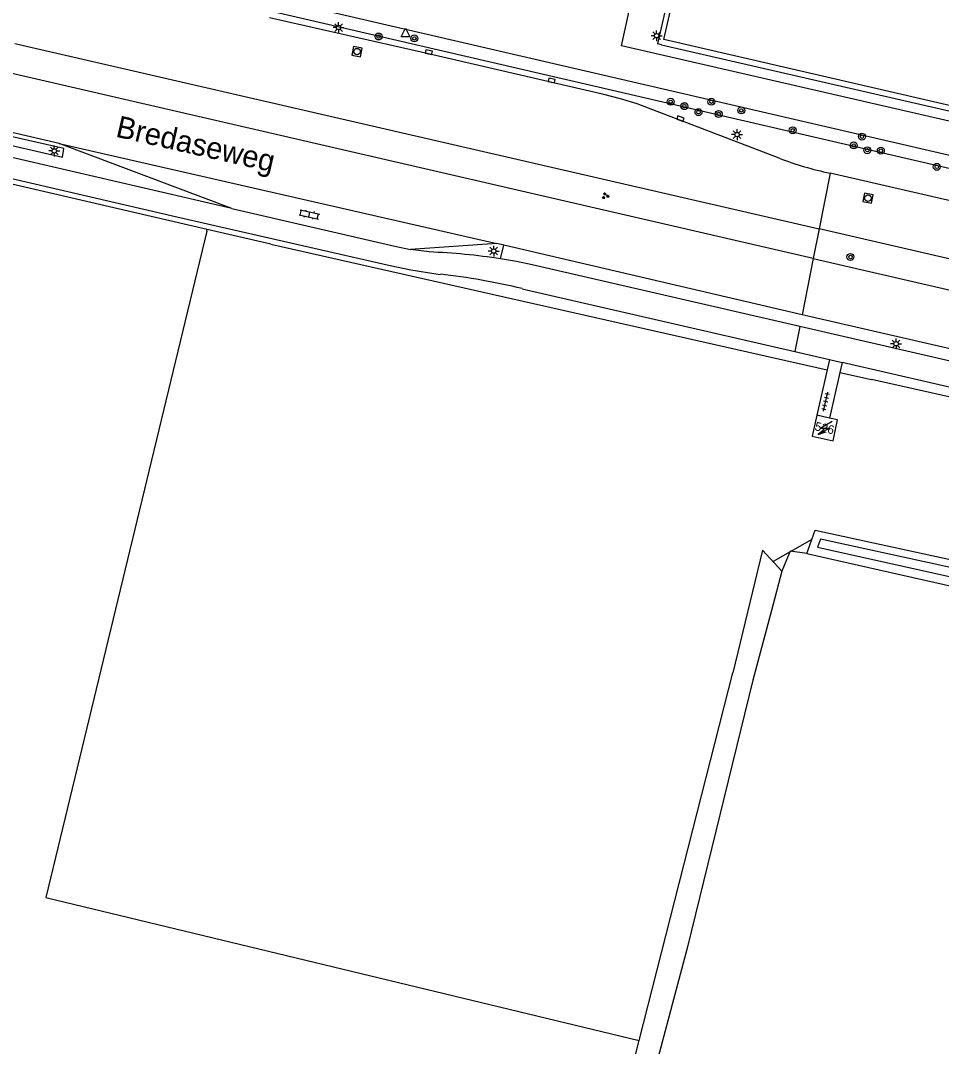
# Model space of a CAD drawing. Extents: x 128999 to 131010, y 395498 to 399007.
# Drawn here: x 129830.6 to 129936.7, y 396799.6 to 396917.8 of the extents above; entities that cross this region are included whole.
import ezdxf

# ---------------------------------------------------------------- set-up
doc = ezdxf.new("R2010")
doc.units = 0
for name, color, linetype in [('gg-afsc-hekwerk', 7, 'Continuous'), ('gg-anno-huisnummerreeks BGT', 7, 'Continuous'), ('gg-anno-openbare ruimte label', 7, 'Continuous'), ('gg-bbg-hoofdgebouw', 7, 'Continuous'), ('gg-knt-verharding', 7, 'Continuous'), ('gg-kntw-bovenkant insteek waterloop', 7, 'Continuous'), ('gg-kntw-waterlijn', 7, 'Continuous'), ('gg-kwrk-duiker nz buis', 7, 'Continuous'), ('gt-grn-groengrens', 7, 'Continuous'), ('gt-grn-weggrens', 7, 'Continuous'), ('gt-symb-boom', 7, 'Continuous'), ('gt-symb-groenvak', 7, 'Continuous'), ('gt-symb-klinker verharding', 7, 'Continuous'), ('gt-symb-kolk', 7, 'Continuous'), ('gt-symb-lichtmast', 7, 'Continuous'), ('gt-symb-rioolschacht', 7, 'Continuous'), ('gt-symb-tegel verharding', 7, 'Continuous'), ('gt-symb-trafo symbool', 7, 'Continuous'), ('gt-symb-waterafsluiter', 7, 'Continuous'), ('gx-grn-maaiveld', 7, 'Continuous')]:
    doc.layers.add(name, color=color, linetype=linetype)

# ---------------------------------------------------------------- blocks, each defined once
blk = doc.blocks.new('gt0-LMAST')
at = {"layer": 'gt-symb-lichtmast'}
for p, q in [((-0.18, 0.17), (-0.45, 0.44)), ((-0.01, 0.25), (-0.01, 0.62)), ((0.17, 0.17), (0.44, 0.44)), ((-0.26, 0), (-0.63, 0)), ((-0.18, -0.18), (-0.45, -0.45)), ((-0.01, -0.25), (-0.01, -0.63)), ((0.44, -0.45), (0.17, -0.18)), ((0.24, 0), (0.62, 0))]:
    blk.add_line(p, q, dxfattribs=at)
blk.add_circle((-0.01, 0), 0.25, dxfattribs=at)
blk = doc.blocks.new('gt0-BOOM')
at = {"layer": 'gt-symb-boom'}
for radius in [0.4, 0.2]:
    blk.add_circle((0, 0), radius, dxfattribs=at)
blk = doc.blocks.new('gt0-KOLK')
at = {"layer": 'gt-symb-kolk'}
blk.add_lwpolyline([(0, 0), (0.38, 0), (0.38, 0.4), (-0.38, 0.4), (-0.38, 0), (0, 0)], dxfattribs=at)
blk = doc.blocks.new('gt0-RS')
at = {"layer": 'gt-symb-rioolschacht'}
blk.add_lwpolyline([(-0.5, -0.5), (0.5, -0.5), (0.5, 0.5), (-0.5, 0.5)], close=True, dxfattribs=at)
blk.add_circle((0, 0), 0.375, dxfattribs=at)
blk = doc.blocks.new('gt0-WAFSL')
at = {"layer": 'gt-symb-waterafsluiter'}
for p, q in [((-0.5, -0.33), (0, 0.67)), ((0, 0.67), (0.5, -0.33)), ((0.5, -0.33), (-0.5, -0.33))]:
    blk.add_line(p, q, dxfattribs=at)
blk = doc.blocks.new('gt0-KL1')
at = {"layer": 'gt-symb-klinker verharding'}
for p, q in [((-1.15, 0.3), (1.15, 0.3)), ((-1, -0.3), (-1, 0.3)), ((-0.5, 0.3), (-0.5, 0.45)), ((0, -0.3), (0, 0.3)), ((0.5, 0.3), (0.5, 0.45)), ((1, -0.3), (1, 0.3)), ((-1.15, -0.3), (1.15, -0.3)), ((-0.5, -0.45), (-0.5, -0.3)), ((0.5, -0.45), (0.5, -0.3))]:
    blk.add_line(p, q, dxfattribs=at)
blk = doc.blocks.new('gt0-GRVAK')
at = {"layer": 'gt-symb-groenvak'}
for p, q in [((-0.11, 0.19), (-0.23, 0.24)), ((-0.18, 0.15), (0.09, 0.15)), ((-0.09, 0.21), (-0.16, 0.32)), ((-0.05, 0.21), (-0.05, 0.39)), ((0, 0.21), (0.06, 0.32)), ((0.01, 0.19), (0.13, 0.24)), ((0.26, -0.05), (0.2, 0.06)), ((0.31, -0.05), (0.31, 0.13)), ((0.35, -0.05), (0.41, 0.06)), ((-0.24, -0.23), (-0.36, -0.18)), ((-0.32, -0.26), (-0.05, -0.26)), ((-0.23, -0.21), (-0.29, -0.1)), ((-0.18, -0.2), (-0.18, -0.02)), ((-0.14, -0.21), (-0.07, -0.1)), ((-0.12, -0.23), (0, -0.18)), ((0.24, -0.07), (0.12, -0.02)), ((0.17, -0.11), (0.44, -0.11)), ((0.37, -0.07), (0.49, -0.02))]:
    blk.add_line(p, q, dxfattribs=at)
blk = doc.blocks.new('gt0-HSP')
at = {"layer": 'gt-symb-trafo symbool'}
for points in [[(0.77, 0.75), (-0.53, 0), (0.47, 0), (-0.83, -0.75)], [(-0.22, -0.24), (-0.83, -0.75), (-0.08, -0.48)]]:
    blk.add_lwpolyline(points, dxfattribs=at)
blk = doc.blocks.new('gt0-TEG1')
at = {"layer": 'gt-symb-tegel verharding'}
for p, q in [((-1.12, 0), (1.12, 0)), ((-0.9, -0.25), (-0.9, 0.25)), ((-0.45, -0.25), (-0.45, 0.25)), ((0, -0.25), (0, 0.25)), ((0.45, -0.25), (0.45, 0.25)), ((0.9, -0.25), (0.9, 0.25))]:
    blk.add_line(p, q, dxfattribs=at)

msp = doc.modelspace()

# ---------------------------------------------------------------- linework, layer by layer
at = {"layer": 'gg-afsc-hekwerk'}
for p, q in [((129904.46, 396915.02), (129961.08, 396901.99)), ((129852.09, 396893.73), (129798.43, 396906.18)), ((129852.09, 396893.73), (129798.43, 396906.18)), ((129859.43, 396892.03), (129852.09, 396893.73)), ((129859.43, 396892.03), (129852.09, 396893.73))]:
    msp.add_line(p, q, dxfattribs=at)
for points in [[(129904.46, 396915.02), (129904.01, 396915.13), (129926.28, 397012.22), (129944.93, 397007.94)], [(129961.99, 396900.62), (129899.85, 396914.88), (129901.75, 396923.71), (129893.46, 396925.54), (129893.84, 396927.48)]]:
    msp.add_lwpolyline(points, dxfattribs=at)
at = {"layer": 'gg-bbg-hoofdgebouw'}
msp.add_line((129923.81, 396871.98), (129922.35, 396872.32), dxfattribs=at)
msp.add_lwpolyline([(129922.35, 396872.32), (129921.79, 396869.92), (129924.21, 396869.37), (129924.74, 396871.77), (129923.81, 396871.98)], dxfattribs=at)
at = {"layer": 'gg-knt-verharding'}
for p, q in [((129921.93, 396890.37), (129811.75, 396915.82)), ((129829.95, 396915.16), (129922.61, 396893.79)), ((129835.03, 396903.64), (129808.32, 396909.88)), ((129798.58, 396906.82), (129848.6, 396895.2)), ((129835.03, 396903.64), (129885.46, 396892.1)), ((129854.94, 396896.15), (129835.03, 396903.64)), ((129976.57, 396888.09), (129923.88, 396900.23)), ((129991.44, 396877.96), (129922.61, 396893.79)), ((129885.46, 396892.1), (129875.51, 396891.44)), ((129886.26, 396891.91), (129885.46, 396892.1)), ((129877.68, 396891.14), (129875.51, 396891.44)), ((129920.65, 396883.88), (129886.26, 396891.91)), ((129921.93, 396890.37), (129990.62, 396874.57)), ((129888.38, 396886.9), (129919.81, 396879.66)), ((129919.81, 396879.66), (129923.81, 396878.74)), ((129923.81, 396878.74), (129923.54, 396877.56)), ((129923.81, 396878.74), (129925.27, 396878.41)), ((129925.27, 396878.41), (129925, 396877.24)), ((129923.54, 396877.56), (129922.35, 396872.32)), ((129925, 396877.24), (129923.81, 396871.98))]:
    msp.add_line(p, q, dxfattribs=at)
for points in [[(129926.73, 397011.51), (129983.36, 396998.53), (129961.2, 396902.58), (129904.71, 396915.61), (129926.73, 397011.51)], [(129918.02, 396901.95), (129901.63, 396908.2), (129899.73, 396908.78), (129897.81, 396909.28), (129877.59, 396913.97), (129859.29, 396918.13)], [(129854.94, 396896.15), (129809.83, 396906.58), (129808.62, 396906.81)], [(129854.94, 396896.15), (129873.72, 396891.81), (129875.51, 396891.44)], [(129848.6, 396895.2), (129873.17, 396889.57), (129875.56, 396889.08), (129878.96, 396888.55)], [(129920.38, 396882.54), (129889.54, 396889.65), (129887.73, 396890.02), (129885.9, 396890.33)], [(130090.42, 396844.78), (130000, 396865.64), (129920.65, 396883.88)], [(130090.09, 396843.43), (130000, 396864.17), (129920.38, 396882.54)], [(130328.39, 396785.64), (130000, 396861.19), (129925.27, 396878.41)]]:
    msp.add_lwpolyline(points, dxfattribs=at)
for centre, radius, start, end in [((129931.37, 396936.5), 37.04, 248.8743, 258.3329), ((129875.09, 396822.68), 68.51, 80.9178, 87.8349), ((129871.15, 396816.17), 72.81, 76.3037, 83.8406)]:
    msp.add_arc(centre, radius, start, end, dxfattribs=at)
at = {"layer": 'gg-kntw-bovenkant insteek waterloop'}
for p, q in [((129918.31, 396854.36), (129917.11, 396849.83)), ((129917.11, 396849.83), (129914.98, 396841.78)), ((129901.86, 396800.25), (129912.65, 396842.64))]:
    msp.add_line(p, q, dxfattribs=at)
for points in [[(129918.31, 396854.36), (129916.1, 396856.75), (129912.65, 396842.64)], [(129914.98, 396841.78), (129907.4, 396810.88), (129901.52, 396788.8), (129891.75, 396746.48), (129886.76, 396727.57)], [(129885.5, 396722.82), (129883.07, 396723.36), (129889.98, 396751.46), (129897.32, 396782.44), (129901.86, 396800.25)]]:
    msp.add_lwpolyline(points, dxfattribs=at)
at = {"layer": 'gg-kntw-waterlijn'}
msp.add_lwpolyline([(129984.76, 396853.77), (129982.71, 396846.2), (129981.68, 396845.44), (129980.18, 396845.51), (129922.77, 396858.02), (129922.42, 396857.11), (129980.65, 396844.18), (129982.08, 396844.15), (129983.75, 396845.55), (129986.06, 396853.36)], dxfattribs=at)
at = {"layer": 'gg-kwrk-duiker nz buis'}
msp.add_line((129921.77, 396858), (129917.3, 396855.45), dxfattribs=at)
at = {"layer": 'gt-grn-groengrens'}
for p, q in [((129859.21, 396918.95), (129977.49, 396891.52)), ((129852.05, 396893.55), (129852.09, 396893.73)), ((129922.61, 396893.79), (129921.93, 396890.37)), ((129859.43, 396892.03), (129923.54, 396877.56)), ((129885.9, 396890.33), (129886.26, 396891.91)), ((129925, 396877.24), (129928.63, 396876.42))]:
    msp.add_line(p, q, dxfattribs=at)
for points in [[(129977.84, 396892.92), (129977.1, 396893.11), (129859.69, 396920.37), (129859.21, 396918.95)], [(129810.77, 396908.66), (129810.58, 396907.78), (129835.44, 396902.06), (129835.56, 396903.08), (129810.77, 396908.66)], [(129852.05, 396893.55), (129833.52, 396816.73), (129901.86, 396800.25)], [(130000, 396860.29), (129976.66, 396865.68), (129928.63, 396876.42)]]:
    msp.add_lwpolyline(points, dxfattribs=at)
at = {"layer": 'gt-grn-weggrens'}
for p, q in [((129923.88, 396900.23), (129922.61, 396893.79)), ((129921.93, 396890.37), (129920.65, 396883.88)), ((129920.38, 396882.54), (129919.81, 396879.66))]:
    msp.add_line(p, q, dxfattribs=at)
at = {"layer": 'gx-grn-maaiveld'}
msp.add_line((129921.21, 396856.38), (129980.44, 396842.97), dxfattribs=at)
for points in [[(129921.21, 396856.38), (129922.14, 396859.09), (129981.08, 396846.26)], [(129921.21, 396856.38), (129919.27, 396856.66), (129918.31, 396854.36)]]:
    msp.add_lwpolyline(points, dxfattribs=at)

# ---------------------------------------------------------------- block references
at = {"layer": 'gt-symb-boom'}
for p in [(129871.85, 396915.97), (129875.97, 396915.75), (129905.51, 396908.45), (129910.2, 396908.45), (129907.09, 396907.94), (129908.71, 396907.25), (129913.65, 396907.45), (129911.03, 396907.04), (129919.57, 396905.16), (129927.54, 396904.43), (129926.6, 396903.42), (129928.17, 396902.86), (129929.72, 396902.82), (129936.17, 396900.95), (129926.22, 396890.56)]:
    msp.add_blockref('gt0-BOOM', p, dxfattribs=at)
at = {"layer": 'gt-symb-groenvak'}
msp.add_blockref('gt0-GRVAK', (129897.97, 396897.6), dxfattribs=at)
at = {"layer": 'gt-symb-klinker verharding', "rotation": -12.882979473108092}
msp.add_blockref('gt0-KL1', (129863.87, 396895.46), dxfattribs=at)
at = {"layer": 'gt-symb-kolk'}
for p, rotation in [((129877.59, 396913.97), -12.702731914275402), ((129891.74, 396910.71), -12.827123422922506), ((129906.56, 396906.32), -20.844264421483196)]:
    msp.add_blockref('gt0-KOLK', p, dxfattribs=dict(at, rotation=rotation))
at = {"layer": 'gt-symb-lichtmast'}
for p in [(129867.24, 396917.01), (129903.89, 396916.06), (129913.16, 396904.67), (129834.48, 396902.78), (129885.12, 396891.24), (129931.48, 396880.55)]:
    msp.add_blockref('gt0-LMAST', p, dxfattribs=at)
at = {"layer": 'gt-symb-rioolschacht'}
for p, rotation in [((129869.36, 396914.23), -11.478482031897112), ((129928.24, 396897.33), -11.13011108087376)]:
    msp.add_blockref('gt0-RS', p, dxfattribs=dict(at, rotation=rotation))
at = {"layer": 'gt-symb-tegel verharding', "rotation": 77.04835288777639}
msp.add_blockref('gt0-TEG1', (129923.36, 396873.87), dxfattribs=at)
at = {"layer": 'gt-symb-trafo symbool'}
msp.add_blockref('gt0-HSP', (129923.34, 396870.83), dxfattribs=at)
at = {"layer": 'gt-symb-waterafsluiter'}
msp.add_blockref('gt0-WAFSL', (129874.96, 396916.27), dxfattribs=at)

# ---------------------------------------------------------------- texts
at = {"layer": 'gg-anno-huisnummerreeks BGT'}
msp.add_text('526', height=1, rotation=347.2, dxfattribs=at).set_placement((129922.04, 396870.6))
at = {"layer": 'gg-anno-openbare ruimte label'}
msp.add_text('Bredaseweg', height=2.5, rotation=347.2, dxfattribs=at).set_placement((129841.45, 396904.44))

doc.saveas('drawing.dxf')
